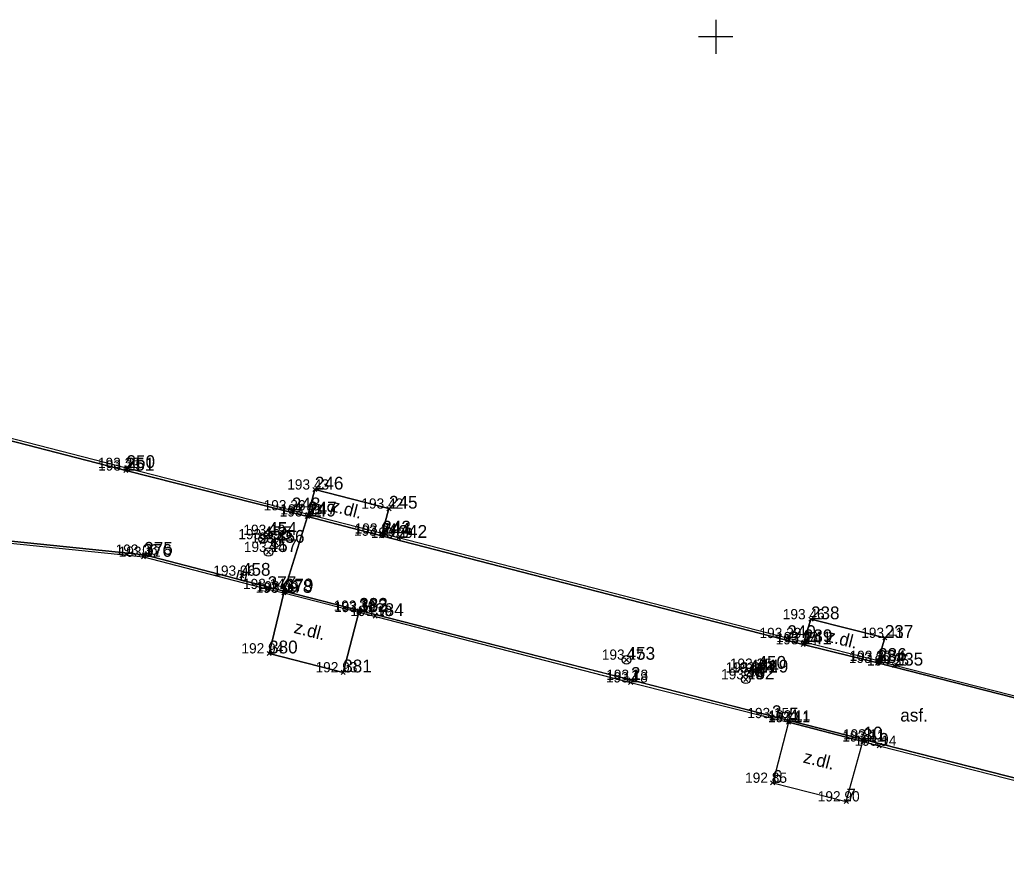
# Model space of a CAD drawing. Extents: x -706861 to -706379, y -1036456 to -1036201.
# Drawn here: x -706690.8 to -706633, y -1036348.1 to -1036299 of the extents above; entities that cross this region are included whole.
import ezdxf

# ---------------------------------------------------------------- set-up
doc = ezdxf.new("R2010")
doc.units = 0
for name, color, linetype in [('18_popisy', 7, 'Continuous'), ('29_vodovod', 7, 'Continuous'), ('30_kanalizace splašková', 7, 'Continuous'), ('40_plochy', 7, 'Continuous'), ('51_body polohopisu_značky', 7, 'Continuous'), ('52_body polohopisu_čísla', 7, 'Continuous'), ('53_body polohopisu_výšky', 7, 'Continuous'), ('54_body polohopisu_čísla nadbytečné pro kreslení', 7, 'Continuous'), ('5_rozhraní ploch', 7, 'Continuous'), ('60_mapový rám_legenda', 7, 'Continuous')]:
    doc.layers.add(name, color=color, linetype=linetype)

msp = doc.modelspace()

# ---------------------------------------------------------------- linework, layer by layer
at = {"layer": '29_vodovod'}
for centre in [(-706676.5, -1036329.43), (-706676.2, -1036329.18), (-706647.55, -1036337.02), (-706647.42, -1036337.24)]:
    msp.add_circle(centre, 0.25, dxfattribs=at)
at = {"layer": '30_kanalizace splašková'}
msp.add_line((-706677.674, -1036331.329), (-706677.806, -1036331.811), dxfattribs=at)
msp.add_lwpolyline([(-706677.916, -1036331.262), (-706678.048, -1036331.745), (-706677.565, -1036331.878), (-706677.432, -1036331.395)], close=True, dxfattribs=at)
for centre in [(-706675.75, -1036329.64), (-706676.18, -1036330.18), (-706655.22, -1036336.49), (-706648.23, -1036337.64), (-706648.04, -1036337.24)]:
    msp.add_circle(centre, 0.25, dxfattribs=at)
at = {"layer": '40_plochy'}
msp.add_lwpolyline([(-706703.07, -1036320.63), (-706684.54, -1036325.41), (-706684.54, -1036325.41), (-706673.91, -1036328.1), (-706675.27, -1036332.47), (-706683.45, -1036330.34), (-706693.55, -1036329.31)], dxfattribs=at)
for points in [[(-706673.86, -1036327.98), (-706673.47, -1036326.52), (-706669.13, -1036327.64), (-706669.52, -1036329.1)], [(-706673.91, -1036328.1), (-706669.56, -1036329.23), (-706644.87, -1036335.59), (-706640.53, -1036336.68), (-706625.407, -1036340.547), (-706626.555, -1036344.932), (-706641.34, -1036341.16), (-706645.7, -1036340.05), (-706670.86, -1036333.6), (-706675.27, -1036332.47)], [(-706675.29, -1036332.57), (-706670.89, -1036333.7), (-706671.81, -1036337.23), (-706676.15, -1036336.12)], [(-706644.42, -1036334.12), (-706640.1, -1036335.21), (-706640.49, -1036336.56), (-706644.84, -1036335.46)], [(-706645.73, -1036340.15), (-706646.66, -1036343.7), (-706642.35, -1036344.79), (-706641.38, -1036341.28)]]:
    msp.add_lwpolyline(points, close=True, dxfattribs=at)
at = {"layer": '51_body polohopisu_značky'}
for points in [[(-706684.66, -1036325.53), (-706684.42, -1036325.29)], [(-706684.66, -1036325.29), (-706684.42, -1036325.53)], [(-706684.62, -1036325.38), (-706684.38, -1036325.14)], [(-706684.62, -1036325.14), (-706684.38, -1036325.38)], [(-706673.59, -1036326.64), (-706673.35, -1036326.4)], [(-706673.59, -1036326.4), (-706673.35, -1036326.64)], [(-706674.94, -1036327.86), (-706674.7, -1036327.62)], [(-706674.94, -1036327.62), (-706674.7, -1036327.86)], [(-706669.25, -1036327.76), (-706669.01, -1036327.52)], [(-706669.25, -1036327.52), (-706669.01, -1036327.76)], [(-706674.03, -1036328.22), (-706673.79, -1036327.98)], [(-706674.03, -1036327.98), (-706673.79, -1036328.22)], [(-706673.99, -1036328.1), (-706673.75, -1036327.86)], [(-706673.99, -1036327.86), (-706673.75, -1036328.1)], [(-706676.62, -1036329.55), (-706676.38, -1036329.31)], [(-706676.62, -1036329.31), (-706676.38, -1036329.55)], [(-706676.32, -1036329.3), (-706676.08, -1036329.06)], [(-706676.32, -1036329.06), (-706676.08, -1036329.3)], [(-706669.68, -1036329.35), (-706669.44, -1036329.11)], [(-706669.68, -1036329.11), (-706669.44, -1036329.35)], [(-706669.64, -1036329.22), (-706669.4, -1036328.98)], [(-706669.64, -1036328.98), (-706669.4, -1036329.22)], [(-706668.69, -1036329.47), (-706668.45, -1036329.23)], [(-706668.69, -1036329.23), (-706668.45, -1036329.47)], [(-706675.87, -1036329.76), (-706675.63, -1036329.52)], [(-706675.87, -1036329.52), (-706675.63, -1036329.76)], [(-706683.63, -1036330.58), (-706683.39, -1036330.34)], [(-706683.63, -1036330.34), (-706683.39, -1036330.58)], [(-706683.58, -1036330.46), (-706683.34, -1036330.22)], [(-706683.58, -1036330.22), (-706683.34, -1036330.46)], [(-706676.3, -1036330.3), (-706676.06, -1036330.06)], [(-706676.3, -1036330.06), (-706676.06, -1036330.3)], [(-706677.86, -1036331.69), (-706677.62, -1036331.45)], [(-706677.86, -1036331.45), (-706677.62, -1036331.69)], [(-706676.35, -1036332.47), (-706676.11, -1036332.23)], [(-706676.35, -1036332.23), (-706676.11, -1036332.47)], [(-706675.41, -1036332.69), (-706675.17, -1036332.45)], [(-706675.41, -1036332.45), (-706675.17, -1036332.69)], [(-706675.35, -1036332.61), (-706675.11, -1036332.37)], [(-706675.35, -1036332.37), (-706675.11, -1036332.61)], [(-706670.99, -1036333.74), (-706670.75, -1036333.5)], [(-706670.99, -1036333.5), (-706670.75, -1036333.74)], [(-706671.01, -1036333.82), (-706670.77, -1036333.58)], [(-706671.01, -1036333.58), (-706670.77, -1036333.82)], [(-706670.06, -1036334.05), (-706669.82, -1036333.81)], [(-706670.06, -1036333.81), (-706669.82, -1036334.05)], [(-706644.54, -1036334.24), (-706644.3, -1036334)], [(-706644.54, -1036334), (-706644.3, -1036334.24)], [(-706645.93, -1036335.34), (-706645.69, -1036335.1)], [(-706645.93, -1036335.1), (-706645.69, -1036335.34)], [(-706640.22, -1036335.33), (-706639.98, -1036335.09)], [(-706640.22, -1036335.09), (-706639.98, -1036335.33)], [(-706644.99, -1036335.71), (-706644.75, -1036335.47)], [(-706644.99, -1036335.47), (-706644.75, -1036335.71)], [(-706644.96, -1036335.58), (-706644.72, -1036335.34)], [(-706644.96, -1036335.34), (-706644.72, -1036335.58)], [(-706676.27, -1036336.24), (-706676.03, -1036336)], [(-706676.27, -1036336), (-706676.03, -1036336.24)], [(-706655.34, -1036336.61), (-706655.1, -1036336.37)], [(-706655.34, -1036336.37), (-706655.1, -1036336.61)], [(-706647.67, -1036337.14), (-706647.43, -1036336.9)], [(-706647.67, -1036336.9), (-706647.43, -1036337.14)], [(-706640.65, -1036336.8), (-706640.41, -1036336.56)], [(-706640.65, -1036336.56), (-706640.41, -1036336.8)], [(-706640.61, -1036336.68), (-706640.37, -1036336.44)], [(-706640.61, -1036336.44), (-706640.37, -1036336.68)], [(-706639.64, -1036336.95), (-706639.4, -1036336.71)], [(-706639.64, -1036336.71), (-706639.4, -1036336.95)], [(-706671.93, -1036337.35), (-706671.69, -1036337.11)], [(-706671.93, -1036337.11), (-706671.69, -1036337.35)], [(-706655.08, -1036337.79), (-706654.84, -1036337.55)], [(-706655.08, -1036337.55), (-706654.84, -1036337.79)], [(-706648.35, -1036337.76), (-706648.11, -1036337.52)], [(-706648.35, -1036337.52), (-706648.11, -1036337.76)], [(-706648.16, -1036337.36), (-706647.92, -1036337.12)], [(-706648.16, -1036337.12), (-706647.92, -1036337.36)], [(-706647.54, -1036337.36), (-706647.3, -1036337.12)], [(-706647.54, -1036337.12), (-706647.3, -1036337.36)], [(-706655.1, -1036337.94), (-706654.86, -1036337.7)], [(-706655.1, -1036337.7), (-706654.86, -1036337.94)], [(-706646.82, -1036340.03), (-706646.58, -1036339.79)], [(-706646.82, -1036339.79), (-706646.58, -1036340.03)], [(-706645.85, -1036340.27), (-706645.61, -1036340.03)], [(-706645.85, -1036340.03), (-706645.61, -1036340.27)], [(-706645.82, -1036340.17), (-706645.58, -1036339.93)], [(-706645.82, -1036339.93), (-706645.58, -1036340.17)], [(-706641.5, -1036341.4), (-706641.26, -1036341.16)], [(-706641.5, -1036341.16), (-706641.26, -1036341.4)], [(-706641.46, -1036341.28), (-706641.22, -1036341.04)], [(-706641.46, -1036341.04), (-706641.22, -1036341.28)], [(-706640.54, -1036341.65), (-706640.3, -1036341.41)], [(-706640.54, -1036341.41), (-706640.3, -1036341.65)], [(-706646.78, -1036343.82), (-706646.54, -1036343.58)], [(-706646.78, -1036343.58), (-706646.54, -1036343.82)], [(-706642.47, -1036344.91), (-706642.23, -1036344.67)], [(-706642.47, -1036344.67), (-706642.23, -1036344.91)]]:
    msp.add_lwpolyline(points, dxfattribs=at)
at = {"layer": '5_rozhraní ploch'}
for points in [[(-706617.25, -1036342.5), (-706639.52, -1036336.83), (-706640.49, -1036336.56), (-706644.84, -1036335.46), (-706645.81, -1036335.22), (-706668.57, -1036329.35), (-706669.52, -1036329.1), (-706673.86, -1036327.98), (-706674.82, -1036327.74), (-706684.5, -1036325.26), (-706698.68, -1036321.62), (-706703.04, -1036320.52), (-706704.01, -1036320.26), (-706706.64, -1036319.62), (-706716.66, -1036318.6), (-706727.29, -1036315.94), (-706728.26, -1036315.7), (-706732.64, -1036314.64), (-706733.62, -1036314.44), (-706736.58, -1036313.83)], [(-706611.97, -1036343.95), (-706616.32, -1036342.87), (-706620.945, -1036341.687), (-706625.407, -1036340.547), (-706640.53, -1036336.68), (-706644.87, -1036335.59), (-706669.56, -1036329.23), (-706673.91, -1036328.1), (-706684.54, -1036325.41), (-706703.07, -1036320.63), (-706706.65, -1036319.75), (-706716.69, -1036318.74), (-706728.29, -1036315.81), (-706732.59, -1036314.76), (-706736.58, -1036313.96)], [(-706734.78, -1036319.22), (-706733.79, -1036319.41), (-706729.37, -1036320.29), (-706728.43, -1036320.56), (-706719.54, -1036322.79), (-706704.23, -1036326.76), (-706703.26, -1036327), (-706698.9, -1036328.11), (-706697.92, -1036328.35), (-706693.6, -1036329.42), (-706683.51, -1036330.46), (-706676.23, -1036332.35), (-706675.29, -1036332.57), (-706670.89, -1036333.7)], [(-706729.35, -1036320.19), (-706703.22, -1036326.89), (-706698.85, -1036327.99), (-706693.55, -1036329.31), (-706683.45, -1036330.34), (-706675.27, -1036332.47)], [(-706669.52, -1036329.1), (-706669.13, -1036327.64), (-706673.47, -1036326.52), (-706673.86, -1036327.98)], [(-706675.29, -1036332.57), (-706676.15, -1036336.12), (-706671.81, -1036337.23), (-706670.89, -1036333.7)], [(-706675.27, -1036332.47), (-706670.86, -1036333.6)], [(-706670.89, -1036333.7), (-706654.98, -1036337.82), (-706646.7, -1036339.91), (-706645.73, -1036340.15), (-706641.38, -1036341.28), (-706640.42, -1036341.53), (-706618.1, -1036347.24)], [(-706670.86, -1036333.6), (-706654.96, -1036337.67), (-706645.7, -1036340.05), (-706641.34, -1036341.16), (-706626.555, -1036344.932), (-706621.962, -1036346.105), (-706617.12, -1036347.34), (-706609.33, -1036349.34), (-706607.89, -1036351.73), (-706591.92, -1036355.83), (-706589.44, -1036354.45), (-706583.46, -1036355.97), (-706564.29, -1036360.86), (-706559.11, -1036363.05), (-706555.02, -1036364.83), (-706530.33, -1036371.14), (-706525.95, -1036372.11), (-706524.99, -1036372.34)], [(-706640.49, -1036336.56), (-706640.1, -1036335.21), (-706644.42, -1036334.12), (-706644.84, -1036335.46)], [(-706645.73, -1036340.15), (-706646.66, -1036343.7), (-706642.35, -1036344.79), (-706641.38, -1036341.28)]]:
    msp.add_lwpolyline(points, dxfattribs=at)
at = {"layer": '60_mapový rám_legenda'}
for points in [[(-706650, -1036299), (-706650, -1036300), (-706650, -1036301)], [(-706649, -1036300), (-706650, -1036300), (-706651, -1036300)]]:
    msp.add_lwpolyline(points, dxfattribs=at)

# ---------------------------------------------------------------- texts
at = {"layer": '18_popisy'}
for rotation, p in [(345.52971, (-706672.59, -1036327.78)), (345.65355, (-706674.745, -1036334.908)), (345.839, (-706643.575, -1036335.406)), (345.80747, (-706644.924, -1036342.502))]:
    msp.add_text('z.dl.', height=0.75, rotation=rotation, dxfattribs=at).set_placement(p)
msp.add_text('asf.', height=0.75, dxfattribs=at).set_placement((-706639.19, -1036340.11))
at = {"layer": '52_body polohopisu_čísla'}
for s, p in [('250', (-706684.5, -1036325.26)), ('246', (-706673.47, -1036326.52)), ('248', (-706674.82, -1036327.74)), ('245', (-706669.13, -1036327.64)), ('456', (-706675.75, -1036329.64)), ('243', (-706669.52, -1036329.1)), ('375', (-706683.46, -1036330.34)), ('377', (-706676.23, -1036332.35)), ('382', (-706670.89, -1036333.7)), ('238', (-706644.42, -1036334.12)), ('237', (-706640.1, -1036335.21)), ('239', (-706644.84, -1036335.46)), ('380', (-706676.15, -1036336.12)), ('453', (-706655.22, -1036336.49)), ('235', (-706639.52, -1036336.83)), ('381', (-706671.81, -1036337.23)), ('449', (-706647.42, -1036337.24)), ('1', (-706654.98, -1036337.82)), ('3', (-706646.7, -1036339.91)), ('4', (-706645.73, -1036340.15)), ('8', (-706641.38, -1036341.28)), ('9', (-706640.42, -1036341.53)), ('6', (-706646.66, -1036343.7)), ('7', (-706642.35, -1036344.79))]:
    msp.add_text(s, height=0.75, dxfattribs=at).set_placement(p)
at = {"layer": '53_body polohopisu_výšky'}
for s, p in [('193 30 ', (-706686.17, -1036325.26)), ('193 25 ', (-706686.158, -1036325.41)), ('193 43 ', (-706675.088, -1036326.52)), ('193 36 ', (-706676.471, -1036327.74)), ('193 42 ', (-706670.748, -1036327.64)), ('193 32 ', (-706675.528, -1036328.1)), ('193 33 ', (-706675.488, -1036327.98)), ('193 19 ', (-706677.953, -1036329.43)), ('193 19 ', (-706677.653, -1036329.18)), ('193 34 ', (-706671.178, -1036329.23)), ('193 34 ', (-706671.138, -1036329.1)), ('193 39 ', (-706670.193, -1036329.35)), ('193 18 ', (-706677.198, -1036329.64)), ('193 06 ', (-706685.137, -1036330.34)), ('193 12 ', (-706684.958, -1036330.46)), ('193 14 ', (-706677.628, -1036330.18)), ('193 06 ', (-706679.417, -1036331.57)), ('193 14 ', (-706677.678, -1036332.35)), ('193 09 ', (-706676.939, -1036332.57)), ('193 09 ', (-706676.879, -1036332.49)), ('193 10 ', (-706672.37, -1036333.62)), ('193 12 ', (-706672.338, -1036333.7)), ('193 19 ', (-706671.393, -1036333.93)), ('193 46 ', (-706646.071, -1036334.12)), ('193 39 ', (-706647.433, -1036335.22)), ('193 41 ', (-706641.477, -1036335.21)), ('193 34 ', (-706646.488, -1036335.59)), ('193 33 ', (-706646.458, -1036335.46)), ('192 94 ', (-706677.77, -1036336.12)), ('193 17 ', (-706656.668, -1036336.49)), ('193 25 ', (-706649.168, -1036337.02)), ('193 30 ', (-706642.2, -1036336.68)), ('193 30 ', (-706642.16, -1036336.56)), ('193 35 ', (-706641.138, -1036336.83)), ('192 93 ', (-706673.43, -1036337.23)), ('193 21 ', (-706649.417, -1036337.24)), ('193 24 ', (-706649.038, -1036337.24)), ('193 18 ', (-706656.428, -1036337.82)), ('193 13 ', (-706656.408, -1036337.67)), ('193 19 ', (-706649.683, -1036337.64)), ('193 15 ', (-706648.148, -1036339.91)), ('193 11 ', (-706646.937, -1036340.15)), ('193 11 ', (-706646.907, -1036340.05)), ('193 11 ', (-706642.587, -1036341.28)), ('193 11 ', (-706642.547, -1036341.16)), ('193 14 ', (-706641.868, -1036341.53)), ('192 85 ', (-706648.278, -1036343.7)), ('192 90 ', (-706644.022, -1036344.79))]:
    msp.add_text(s, height=0.6, dxfattribs=at).set_placement(p)
at = {"layer": '54_body polohopisu_čísla nadbytečné pro kreslení'}
for s, p in [('251', (-706684.54, -1036325.41)), ('249', (-706673.91, -1036328.1)), ('247', (-706673.87, -1036327.98)), ('455', (-706676.5, -1036329.43)), ('454', (-706676.2, -1036329.18)), ('244', (-706669.56, -1036329.23)), ('242', (-706668.57, -1036329.35)), ('457', (-706676.18, -1036330.18)), ('376', (-706683.51, -1036330.46)), ('458', (-706677.74, -1036331.57)), ('379', (-706675.23, -1036332.49)), ('378', (-706675.29, -1036332.57)), ('383', (-706670.87, -1036333.62)), ('384', (-706669.94, -1036333.93)), ('240', (-706645.81, -1036335.22)), ('241', (-706644.87, -1036335.59)), ('236', (-706640.49, -1036336.56)), ('450', (-706647.55, -1036337.02)), ('234', (-706640.53, -1036336.68)), ('2', (-706654.96, -1036337.67)), ('452', (-706648.23, -1036337.64)), ('451', (-706648.04, -1036337.24)), ('5', (-706645.7, -1036340.05)), ('10', (-706641.34, -1036341.16))]:
    msp.add_text(s, height=0.75, dxfattribs=at).set_placement(p)

doc.saveas('drawing.dxf')
